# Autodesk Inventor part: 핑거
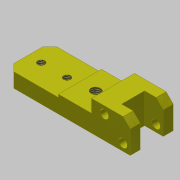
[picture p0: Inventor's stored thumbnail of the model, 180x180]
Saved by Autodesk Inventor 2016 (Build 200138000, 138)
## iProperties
Created: 2019-02
Part Number: 핑거
Material: 알루미늄 6061
Document SubType Name: Modeling
Designer: mduedu
Density: 1 g/cm^3
Appearance: 노란색
Author: mduedu
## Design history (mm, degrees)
sketch "스케치1"
  geometry: L1 (0, 0)-(-86, 0); L2 (-86, 0)-(-86, 21); L3 (-86, 21)-(0, 21); L4 (0, 21)-(0, 0)
  constraints: 8 end point, 2 parallel, 1 horizontal, 1 perpendicular
  dimensions: "d0" = 86 distance of L2.end L3.end; "d1" = 21 distance of L1.end L2.end
extrude "돌출1" new body sketch "스케치1" stored distance "d2" = 30; taper "d3" = 0 deg
sketch "스케치2"
  geometry: L1 (-86, 0)-(0, 0) reference; L2 (0, 0)-(0, 21) reference; L3 (0, 21)-(-86, 21) reference; L4 (-86, 21)-(-86, 0) reference; L5 (-86, 10)-(-50, 10); L6 (-50, 10)-(-50, 21); L7 (-50, 21)-(-86, 21); L8 (-86, 21)-(-86, 10); L9 (-50, 12)-(-27, 12); L10 (-27, 12)-(-27, 21); L11 (-27, 21)-(-50, 21); L12 (-50, 21)-(-50, 12); 1 further point
  constraints: 16 end point, 4 parallel, 4 point on line, 2 horizontal, 2 perpendicular
  dimensions: "d4" = 27 distance between parallel lines of L10 L2; "d5" = 12 distance between parallel lines of L1 L9; "d6" = 36 distance between parallel lines of L6 L4; "d7" = 10 distance between parallel lines of L1 L5
extrude "돌출2" cut sketch "스케치2" stored distance "d8" = 30; taper "d9" = 0 deg
chamfer "모따기1" distance "d10" = 5; stored, may be unused: second distance "d11" = 2, angle "d12" = 45 deg
sketch "스케치3"
  geometry: L1 (27, 0)-(27, 30) reference; L2 (27, 23)-(14, 23); L3 (14, 23)-(14, 7); L4 (14, 7)-(27, 7); L5 (27, 7)-(27, 23); 2 further points
  constraints: 8 end point, 2 midpoint, 2 parallel, 1 horizontal, 1 perpendicular, 1 point on line
  dimensions: "d13" = 16 distance between parallel lines of L4 L2; "d15" = 13 distance of L2.start L2.end
extrude "돌출3" cut sketch "스케치3" stored distance "d16" = 30; taper "d17" = 0 deg
sketch "스케치4"
  geometry: 3 further points
  dimensions: "d18" = 5 horizontal distance of point (-5, 5) point (0, 0); "d19" = 5 horizontal distance of point (-5, 5) point (0, 0); "d20" = 11 vertical distance of point (-18, 16) point (-5, 5); "d21" = 13 horizontal distance of point (-18, 16) point (-5, 5)
hole "구멍1" sketch "스케치4" at (-5, 5), (-18, 16) diameter "d22" = 6; stored, may be unused: countersink angle "d26" = 90 deg, drill point angle "d28" = 118 deg; dims "d23" = 6, "d24" = 4, "d25" = 2, "d27" = 8
sketch "스케치5"
  geometry: L1 (0, 0)-(0, 30) reference; 3 further points
  constraints: 2 horizontal alignment
  dimensions: "d29" = 9 distance from line of point (9, 15) L1; "d30" = 18 distance of point (27, 15) point (9, 15)
hole "구멍2" sketch "스케치5" diameter "d31" = 4.917; stored, may be unused: countersink angle "d35" = 90 deg, drill point angle "d37" = 118 deg; dims "d32" = 6, "d33" = 4, "d34" = 2, "d36" = 8
sketch "스케치6"
  geometry: 3 further points
  constraints: 1 horizontal alignment
  dimensions: "d38" = 20 distance of point (11, 15) point (-9, 15)
hole "구멍3" sketch "스케치6" at (11, 15) diameter "d39" = 6.647; stored, may be unused: countersink angle "d43" = 90 deg, drill point angle "d45" = 118 deg; dims "d40" = 6, "d41" = 4, "d42" = 2, "d44" = 8
chamfer "모따기2" distance "d46" = 5; stored, may be unused: second distance "d47" = 2, angle "d48" = 45 deg
node "솔리드1"
node "투영된 루프1"
